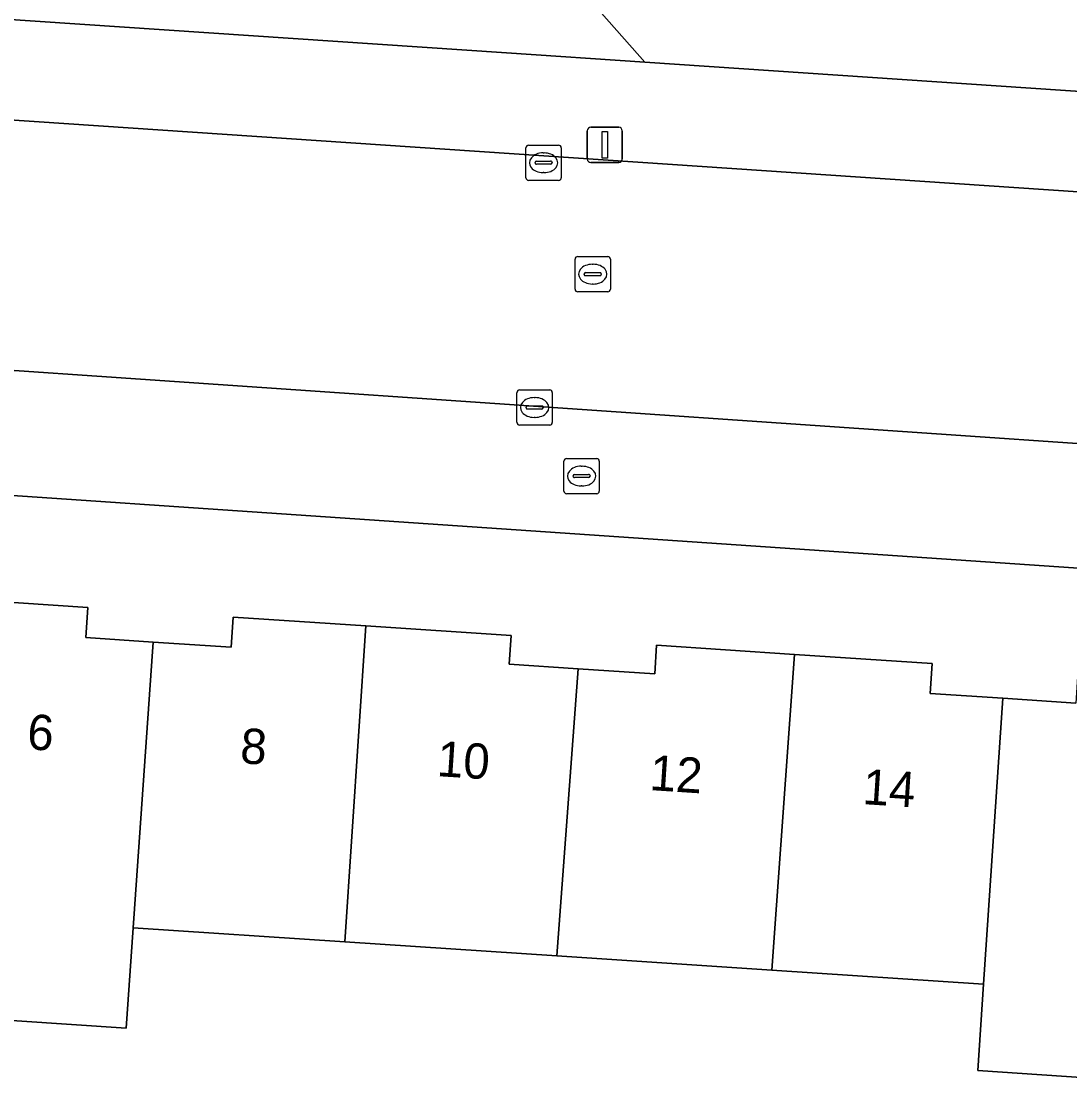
# Model space of a CAD drawing. Extents: x 161848 to 162726, y 385382 to 386521.
# Drawn here: x 162258.76 to 162288.48, y 385578.01 to 385608.15 of the extents above; entities that cross this region are included whole.
import ezdxf

# ---------------------------------------------------------------- set-up
doc = ezdxf.new("R2010")
doc.units = 0
for name, color, linetype in [('IMGEO_Brandkraan', 7, 'Continuous'), ('IMGEO_Erf', 7, 'Continuous'), ('IMGEO_Groenvoorziening', 7, 'Continuous'), ('IMGEO_Kolk', 7, 'Continuous'), ('IMGEO_Lichtmast', 7, 'Continuous'), ('IMGEO_Pand', 7, 'Continuous'), ('IMGEO_Pand_nummerreeks', 7, 'Continuous'), ('IMGEO_Rijbaan_lokaal_open', 7, 'Continuous'), ('IMGEO_Rioolput', 7, 'Continuous'), ('IMGEO_Voetpad_open', 7, 'Continuous')]:
    doc.layers.add(name, color=color, linetype=linetype)

msp = doc.modelspace()

# ---------------------------------------------------------------- linework, layer by layer
at = {"layer": 'IMGEO_Brandkraan'}
for p, q in [((162274.145, 385594.833), (162274.145, 385595.685)), ((162274.22, 385595.759), (162275.072, 385595.759)), ((162274.633, 385595.539), (162274.658, 385595.539)), ((162275.146, 385595.685), (162275.146, 385594.833)), ((162274.404, 385595.253), (162274.404, 385595.265)), ((162274.842, 385595.216), (162274.444, 385595.216)), ((162274.447, 385595.302), (162274.845, 385595.302)), ((162274.888, 385595.265), (162274.888, 385595.253)), ((162274.656, 385594.979), (162274.631, 385594.979)), ((162275.072, 385594.759), (162274.22, 385594.759))]:
    msp.add_line(p, q, dxfattribs=at)
for points in [[(162274.145, 385594.833), (162274.145, 385595.685)], [(162274.22, 385595.759), (162275.072, 385595.759)], [(162275.146, 385595.685), (162275.146, 385594.833)], [(162275.072, 385594.759), (162274.22, 385594.759)]]:
    msp.add_lwpolyline(points, dxfattribs=at)
for centre, radius, start, end in [((162274.222, 385595.683), 0.0765, 91.552, 178.448), ((162274.222, 385595.683), 0.0765, 91.552, 178.448), ((162275.07, 385595.683), 0.0765, 1.552, 88.448), ((162275.07, 385595.683), 0.0765, 1.552, 88.448), ((162274.444, 385595.262), 0.0403, 85.8775, 175.7526), ((162274.441, 385595.252), 0.0366, 178.938, 274.7102), ((162274.845, 385595.259), 0.043, 264.8664, 352.4533), ((162274.849, 385595.264), 0.0386, 1.7309, 96.639), ((162274.222, 385594.835), 0.0765, 181.552, 268.448), ((162274.222, 385594.835), 0.0765, 181.552, 268.448), ((162275.07, 385594.835), 0.0765, 271.552, 358.448), ((162275.07, 385594.835), 0.0765, 271.552, 358.448)]:
    msp.add_arc(centre, radius, start, end, dxfattribs=at)
for centre, major_axis, ratio, start_param, end_param in [((162274.632, 385595.259), (-0.387, 0.002), 0.722429, 4.712389, 7.853982), ((162274.657, 385595.259), (-0.39, 0.002), 0.717154, 1.570796, 4.712389)]:
    msp.add_ellipse(centre, major_axis=major_axis, ratio=ratio, start_param=start_param, end_param=end_param, dxfattribs=at)
at = {"layer": 'IMGEO_Erf'}
for points in [[(162310.902, 385591.138), (162245.477, 385595.597), (162240.397, 385595.895)], [(162256.56, 385591.808), (162260.643, 385591.538), (162260.586, 385590.683), (162262.499, 385590.556), (162264.71, 385590.41), (162264.766, 385591.264), (162268.526, 385591.015), (162272.649, 385590.742), (162272.595, 385589.925), (162274.544, 385589.796), (162276.717, 385589.652), (162276.771, 385590.465), (162280.682, 385590.206), (162284.582, 385589.948), (162284.526, 385589.098), (162286.584, 385588.962), (162288.657, 385588.824)], [(162291.876, 385578.007), (162285.874, 385578.411), (162286.039, 385580.858), (162280.038, 385581.255), (162273.943, 385581.658), (162267.932, 385582.055), (162261.928, 385582.452), (162261.731, 385579.608), (162255.667, 385580.014), (162255.897, 385582.851), (162249.909, 385583.247), (162249.849, 385582.448), (162242.219, 385582.952), (162242.524, 385587.565)]]:
    msp.add_lwpolyline(points, dxfattribs=at)
at = {"layer": 'IMGEO_Groenvoorziening'}
msp.add_lwpolyline([(162207.691, 385617.583), (162238.934, 385615.73), (162238.603, 385609.542), (162272.52, 385607.256), (162276.436, 385606.992), (162274.554, 385609.13), (162272.639, 385611.354), (162271.835, 385611.556), (162265.291, 385613.054), (162261.033, 385614.788), (162259.693, 385616.365), (162259.535, 385620.15), (162259.85, 385621.49), (162261.506, 385623.382), (162263.398, 385624.644), (162247.273, 385625.615), (162234.846, 385626.802), (162223.404, 385627.699)], dxfattribs=at)
msp.add_lwpolyline([(162313.914, 385618.371), (162310.525, 385618.197), (162307.227, 385618.391), (162299.207, 385618.52), (162290.024, 385619.62), (162287.372, 385623.112), (162282.522, 385621.172), (162278.641, 385622.853), (162272.521, 385624.409), (162263.398, 385624.644), (162261.506, 385623.382), (162259.85, 385621.49), (162259.535, 385620.15), (162259.693, 385616.365), (162261.033, 385614.788), (162265.291, 385613.054), (162271.835, 385611.556), (162272.639, 385611.354), (162274.554, 385609.13), (162276.436, 385606.992), (162319.231, 385604.108), (162319.8, 385609.337), (162317.424, 385614.541)], close=True, dxfattribs=at)
at = {"layer": 'IMGEO_Kolk'}
for p, q in [((162273.067, 385603.715), (162273.067, 385604.567)), ((162273.142, 385604.641), (162273.994, 385604.641)), ((162274.068, 385604.567), (162274.068, 385603.715)), ((162273.555, 385604.421), (162273.58, 385604.421)), ((162273.326, 385604.135), (162273.326, 385604.147)), ((162273.764, 385604.098), (162273.366, 385604.098)), ((162273.369, 385604.184), (162273.767, 385604.184)), ((162273.81, 385604.147), (162273.81, 385604.135)), ((162273.994, 385603.641), (162273.142, 385603.641)), ((162273.578, 385603.861), (162273.553, 385603.861)), ((162272.813, 385596.778), (162272.813, 385597.63)), ((162272.888, 385597.704), (162273.74, 385597.704)), ((162273.814, 385597.63), (162273.814, 385596.778)), ((162273.301, 385597.484), (162273.326, 385597.484)), ((162273.072, 385597.198), (162273.072, 385597.21)), ((162273.51, 385597.161), (162273.112, 385597.161)), ((162273.115, 385597.247), (162273.513, 385597.247)), ((162273.556, 385597.21), (162273.556, 385597.198)), ((162273.74, 385596.704), (162272.888, 385596.704)), ((162273.324, 385596.924), (162273.299, 385596.924))]:
    msp.add_line(p, q, dxfattribs=at)
for points in [[(162273.067, 385603.715), (162273.067, 385604.567)], [(162273.142, 385604.641), (162273.994, 385604.641)], [(162274.068, 385604.567), (162274.068, 385603.715)], [(162273.994, 385603.641), (162273.142, 385603.641)], [(162272.813, 385596.778), (162272.813, 385597.63)], [(162272.888, 385597.704), (162273.74, 385597.704)], [(162273.814, 385597.63), (162273.814, 385596.778)], [(162273.74, 385596.704), (162272.888, 385596.704)]]:
    msp.add_lwpolyline(points, dxfattribs=at)
for centre, radius, start, end in [((162273.144, 385604.565), 0.0765, 91.552, 178.448), ((162273.144, 385604.565), 0.0765, 91.552, 178.448), ((162273.992, 385604.565), 0.0765, 1.552, 88.448), ((162273.992, 385604.565), 0.0765, 1.552, 88.448), ((162273.366, 385604.144), 0.0403, 85.8775, 175.7526), ((162273.363, 385604.134), 0.0366, 178.938, 274.7102), ((162273.767, 385604.141), 0.043, 264.8664, 352.4533), ((162273.771, 385604.146), 0.0386, 1.7309, 96.639), ((162273.144, 385603.717), 0.0765, 181.552, 268.448), ((162273.144, 385603.717), 0.0765, 181.552, 268.448), ((162273.992, 385603.717), 0.0765, 271.552, 358.448), ((162273.992, 385603.717), 0.0765, 271.552, 358.448), ((162272.89, 385597.628), 0.0765, 91.552, 178.448), ((162272.89, 385597.628), 0.0765, 91.552, 178.448), ((162273.738, 385597.628), 0.0765, 1.552, 88.448), ((162273.738, 385597.628), 0.0765, 1.552, 88.448), ((162273.112, 385597.207), 0.0403, 85.8775, 175.7526), ((162273.109, 385597.197), 0.0366, 178.938, 274.7102), ((162273.513, 385597.204), 0.043, 264.8664, 352.4533), ((162273.517, 385597.209), 0.0386, 1.7309, 96.639), ((162272.89, 385596.78), 0.0765, 181.552, 268.448), ((162272.89, 385596.78), 0.0765, 181.552, 268.448), ((162273.738, 385596.78), 0.0765, 271.552, 358.448), ((162273.738, 385596.78), 0.0765, 271.552, 358.448)]:
    msp.add_arc(centre, radius, start, end, dxfattribs=at)
for centre, major_axis, ratio, start_param, end_param in [((162273.554, 385604.141), (-0.387, 0.002), 0.722429, 4.712389, 7.853982), ((162273.579, 385604.141), (-0.39, 0.002), 0.717154, 1.570796, 4.712389), ((162273.3, 385597.204), (-0.387, 0.002), 0.722429, 4.712389, 7.853982), ((162273.325, 385597.204), (-0.39, 0.002), 0.717154, 1.570796, 4.712389)]:
    msp.add_ellipse(centre, major_axis=major_axis, ratio=ratio, start_param=start_param, end_param=end_param, dxfattribs=at)
at = {"layer": 'IMGEO_Lichtmast'}
for p, q in [((162274.907, 385605.148), (162275.697, 385605.148)), ((162275.697, 385605.148), (162274.907, 385605.148)), ((162274.807, 385604.248), (162274.807, 385605.048)), ((162274.807, 385605.048), (162274.807, 385604.248)), ((162275.797, 385605.048), (162275.797, 385604.248)), ((162275.797, 385604.248), (162275.797, 385605.048)), ((162275.697, 385604.148), (162274.907, 385604.148)), ((162274.907, 385604.148), (162275.697, 385604.148))]:
    msp.add_line(p, q, dxfattribs=at)
msp.add_lwpolyline([(162275.227, 385605.023), (162275.377, 385605.023), (162275.377, 385604.273), (162275.227, 385604.273), (162275.227, 385605.023)], dxfattribs=at)
for centre, start, end in [((162274.907, 385605.048), 90, 180), ((162274.907, 385605.048), 90, 180), ((162275.697, 385605.048), 0, 90), ((162275.697, 385605.048), 360, 90), ((162274.907, 385604.248), 180, 270), ((162274.907, 385604.248), 180, 270), ((162275.697, 385604.248), 270, 0), ((162275.697, 385604.248), 270, 0)]:
    msp.add_arc(centre, 0.1, start, end, dxfattribs=at)
at = {"layer": 'IMGEO_Pand'}
for points in [[(162262.499, 385590.556), (162260.586, 385590.683), (162260.643, 385591.538), (162256.56, 385591.808), (162255.897, 385582.851), (162255.667, 385580.014), (162261.731, 385579.608), (162261.928, 385582.452)], [(162268.526, 385591.015), (162264.766, 385591.264), (162264.71, 385590.41), (162262.499, 385590.556), (162261.928, 385582.452), (162267.932, 385582.055)], [(162267.932, 385582.055), (162273.943, 385581.658), (162274.544, 385589.796), (162272.595, 385589.925), (162272.649, 385590.742), (162268.526, 385591.015)], [(162280.682, 385590.206), (162276.771, 385590.465), (162276.717, 385589.652), (162274.544, 385589.796), (162273.943, 385581.658), (162280.038, 385581.255)], [(162280.038, 385581.255), (162286.039, 385580.858), (162286.584, 385588.962), (162284.526, 385589.098), (162284.582, 385589.948), (162280.682, 385590.206)], [(162292.662, 385589.463), (162288.716, 385589.724), (162288.657, 385588.824), (162286.584, 385588.962), (162286.039, 385580.858), (162285.874, 385578.411), (162291.876, 385578.007), (162292.044, 385580.461)]]:
    msp.add_lwpolyline(points, close=True, dxfattribs=at)
at = {"layer": 'IMGEO_Rijbaan_lokaal_open'}
for points in [[(162250.141, 385605.918), (162241.588, 385606.517), (162240.952, 385599.422), (162246.169, 385599.107), (162309.752, 385594.736), (162328.221, 385593.475)], [(162392.515, 385589.122), (162412.585, 385587.758), (162415.011, 385587.593), (162431.505, 385586.582), (162435.655, 385586.297), (162436.128, 385593.403), (162432.653, 385593.623), (162250.141, 385605.918)]]:
    msp.add_lwpolyline(points, dxfattribs=at)
at = {"layer": 'IMGEO_Rioolput'}
for p, q in [((162274.459, 385600.558), (162274.459, 385601.41)), ((162274.534, 385601.484), (162275.386, 385601.484)), ((162274.947, 385601.264), (162274.972, 385601.264)), ((162275.46, 385601.41), (162275.46, 385600.558)), ((162274.718, 385600.978), (162274.718, 385600.99)), ((162275.156, 385600.941), (162274.758, 385600.941)), ((162274.761, 385601.027), (162275.159, 385601.027)), ((162275.202, 385600.99), (162275.202, 385600.978)), ((162274.97, 385600.704), (162274.945, 385600.704)), ((162275.386, 385600.484), (162274.534, 385600.484))]:
    msp.add_line(p, q, dxfattribs=at)
for points in [[(162274.459, 385600.558), (162274.459, 385601.41)], [(162274.534, 385601.484), (162275.386, 385601.484)], [(162275.46, 385601.41), (162275.46, 385600.558)], [(162275.386, 385600.484), (162274.534, 385600.484)]]:
    msp.add_lwpolyline(points, dxfattribs=at)
for centre, radius, start, end in [((162274.536, 385601.408), 0.0765, 91.552, 178.448), ((162274.536, 385601.408), 0.0765, 91.552, 178.448), ((162275.384, 385601.408), 0.0765, 1.552, 88.448), ((162275.384, 385601.408), 0.0765, 1.552, 88.448), ((162274.758, 385600.987), 0.0403, 85.8775, 175.7526), ((162274.755, 385600.977), 0.0366, 178.938, 274.7102), ((162275.159, 385600.984), 0.043, 264.8664, 352.4533), ((162275.163, 385600.989), 0.0386, 1.7309, 96.639), ((162274.536, 385600.56), 0.0765, 181.552, 268.448), ((162274.536, 385600.56), 0.0765, 181.552, 268.448), ((162275.384, 385600.56), 0.0765, 271.552, 358.448), ((162275.384, 385600.56), 0.0765, 271.552, 358.448)]:
    msp.add_arc(centre, radius, start, end, dxfattribs=at)
for centre, major_axis, ratio, start_param, end_param in [((162274.946, 385600.984), (-0.387, 0.002), 0.722429, 4.712389, 7.853982), ((162274.971, 385600.984), (-0.39, 0.002), 0.717154, 1.570796, 4.712389)]:
    msp.add_ellipse(centre, major_axis=major_axis, ratio=ratio, start_param=start_param, end_param=end_param, dxfattribs=at)
at = {"layer": 'IMGEO_Voetpad_open'}
for points in [[(162416.342, 385597.564), (162327.188, 385603.572), (162319.231, 385604.108), (162276.436, 385606.992), (162272.52, 385607.256), (162238.603, 385609.542), (162225.673, 385610.463), (162225.228, 385604.48), (162224.178, 385588.393)], [(162234.379, 385607.022), (162241.588, 385606.517), (162250.141, 385605.918), (162432.653, 385593.623), (162436.128, 385593.403), (162437.247, 385593.361)], [(162309.752, 385594.736), (162246.169, 385599.107), (162240.952, 385599.422)], [(162235.023, 385596.21), (162240.397, 385595.895), (162245.477, 385595.597), (162310.902, 385591.138)]]:
    msp.add_lwpolyline(points, dxfattribs=at)

# ---------------------------------------------------------------- texts
at = {"layer": 'IMGEO_Pand_nummerreeks'}
for s, rotation, p in [('6', 356.2471, (162258.906, 385587.52)), ('8', 356.2455, (162264.946, 385587.124)), ('10', 356.2455, (162270.523, 385586.757)), ('12', 356.2455, (162276.553, 385586.361)), ('14', 356.2455, (162282.592, 385585.964))]:
    msp.add_text(s, height=1, rotation=rotation, dxfattribs=at).set_placement(p)

doc.saveas('drawing.dxf')
